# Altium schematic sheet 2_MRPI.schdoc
size 307 x 218 mm; Symbol: Drawing-Symbol_A4; Device: Drawing-Symbol_A4; @Project Name: Avian; @Page Count: 2; @Update Date: 2026-02-01; @Create Date: 2026-01-29; @Schematic Name: Avian_1; @Page No: 2; @Page Name: MRPI; Company: EasyEDA.com; Version: V1.0; Page Size: A4; @Create Time: 14:50:30; @Update Time: 21:39:11; Width: 1170; Height: 825; Region Start: 1; X Region Count: 6; Y Region Count: 4; Blade Width: 10; Title Block Position: 3; @Board Name: Avian_1
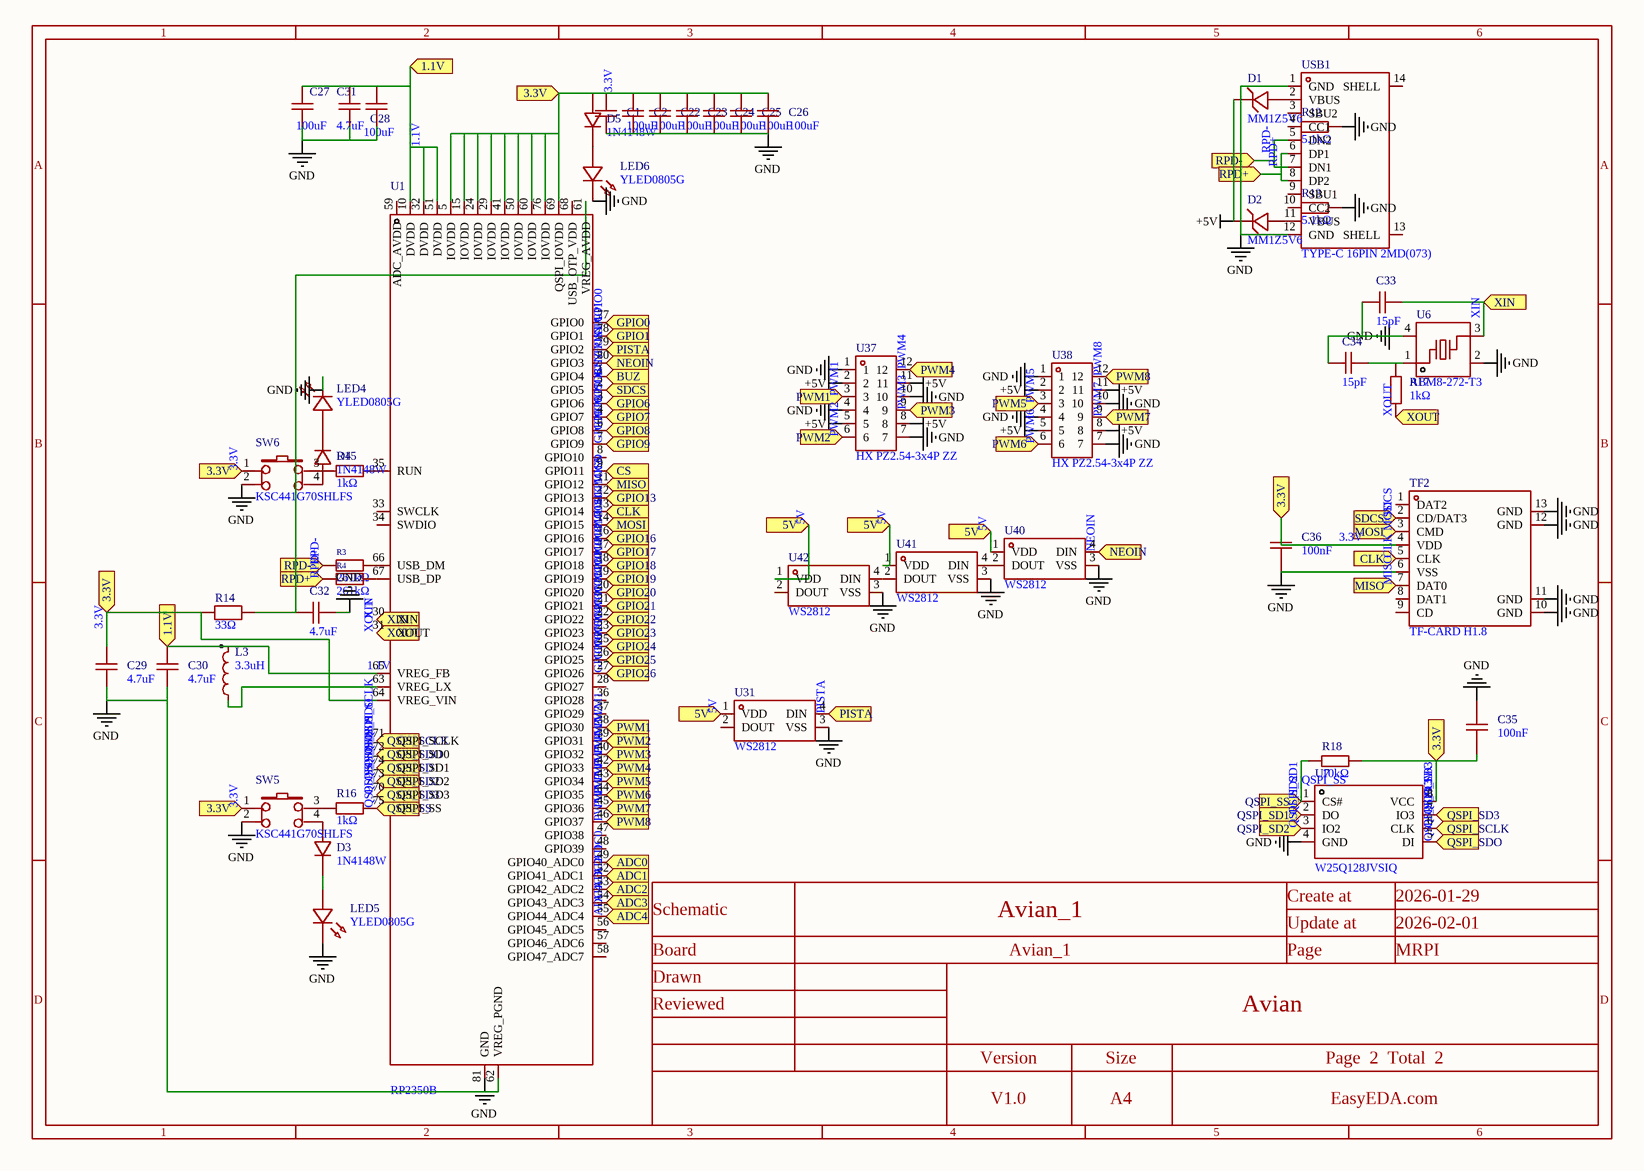
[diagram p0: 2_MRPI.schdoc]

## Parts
C1  100uF  [C1206]
C2  100uF  [C1206]
C22  100uF  [C1206]
C23  100uF  [C1206]
C24  100uF  [C1206]
C25  100uF  [C1206]
C26  100uF  [C1206]
C27  100uF  [C1206]
C28  100uF  [C1206]
C29  4.7uF  [C1206]
C30  4.7uF  [C1206]
C31  4.7uF  [C1206]
C32  4.7uF  [C1206]
C33  15pF  [C0603]
C34  15pF  [C0603]
C35  100nF  [C0603]
C36  100nF  [C0603]
D1  MM1Z5V6  [SOD-123_L2.8-W1.8-LS3.7-RD]
D2  MM1Z5V6  [SOD-123_L2.8-W1.8-LS3.7-RD]
D3  1N4148W  [SOD-123F_L2.7-W1.6-LS3.8-RD]
D4  1N4148W  [SOD-123F_L2.7-W1.6-LS3.8-RD]
D5  1N4148W  [SOD-123F_L2.7-W1.6-LS3.8-RD]
L3  3.3uH  [IND-SMD_L2.0-W1.6_AOTA-B201610S3R3-101-T]
LED4  YLED0805G  [LED0805-FD-GREEN]
LED5  YLED0805G  [LED0805-FD-GREEN]
LED6  YLED0805G  [LED0805-FD-GREEN]
R3  261kΩ  [R0603]
R4  261kΩ  [R0603]
R12  5.1kΩ  [R0805]
R13  5.1kΩ  [R0805]
R14  33Ω  [R0603]
R15  1kΩ  [R0603]
R16  1kΩ  [R0603]
R17  1kΩ  [R0603]
R18  10kΩ  [R0603]
SW5  KSC441G70SHLFS  [KEY--SMD_4P-L6.2-W6.2-P4.50-LS12.0]
SW6  KSC441G70SHLFS  [KEY--SMD_4P-L6.2-W6.2-P4.50-LS12.0]
TF2  TF-CARD H1.8  [TF-SMD_TF-CARD-H1.8]
U1  RP2350B  [QFN-80_L10.0-W10.0-P0.40-TL-EP3.4]
U6  ABM8-272-T3  [CRYSTAL-SMD_4P-L3.2-W2.5-BL]
U7  W25Q128JVSIQ  [SOIC-8_L5.3-W5.3-P1.27-LS8.0-BL]
U31  WS2812  [LED-SMD_4P-L5.0-W5.0-TL-A]
U37  HX PZ2.54-3x4P ZZ  [HDR-TH_12P-P2.54-V-M-R3-C4-S2.54]
U38  HX PZ2.54-3x4P ZZ  [HDR-TH_12P-P2.54-V-M-R3-C4-S2.54]
U40  WS2812  [LED-SMD_4P-L5.0-W5.0-TL-A]
U41  WS2812  [LED-SMD_4P-L5.0-W5.0-TL-A]
U42  WS2812  [LED-SMD_4P-L5.0-W5.0-TL-A]
USB1  TYPE-C 16PIN 2MD(073)  [USB-C-SMD_TYPE-C-6PIN-2MD-073]

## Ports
1.1V (in), 3.3V (in), 5V (in), ADC0 (in), ADC1 (in), ADC2 (in), ADC3 (in), ADC4 (in), BUZ (in), CLK (in), CS (in), GPIO0 (in), GPIO1 (in), GPIO6 (in), GPIO7 (in), GPIO8 (in), GPIO9 (in), GPIO13 (in), GPIO16 (in), GPIO17 (in), GPIO18 (in), GPIO19 (in), GPIO20 (in), GPIO21 (in), GPIO22 (in), GPIO23 (in), GPIO24 (in), GPIO25 (in), GPIO26 (in), MISO (in), MOSI (in), NEOIN (in), PISTA (in), PWM1 (in), PWM2 (in), PWM3 (in), PWM4 (in), PWM5 (in), PWM6 (in), PWM7 (in), PWM8 (in), QSPI_SCLK (in), QSPI_SD1 (in), QSPI_SD2 (in), QSPI_SD3 (in), QSPI_SDO (in), QSPI_SS (in), RPD+ (in), RPD- (in), SDCS (in), XIN (in), XOUT (in)

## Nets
+5V: D1.1(K) D2.1(K) U37.2 U37.5 U37.8 U37.11 U38.2 U38.5 U38.8 U38.11
GND: C1.1 C2.1 C22.1 C23.1 C24.1 C25.1 C26.1 C27.1 C28.1 C29.1 C30.1 C31.1 C32.2 C33.1 C34.1 C35.2 C36.1 LED4.2(K) LED5.2(K) LED6.2(K) R12.2 R13.2 SW5.2 SW6.2 TF2.6(VSS) TF2.10(GND) TF2.11(GND) TF2.12(GND) TF2.13(GND) U1.62(VREG_PGND) U1.81(GND) U6.2(GND) U6.4(GND) U7.4(GND) U31.3(VSS) U37.1 U37.4 U37.7 U37.10 U38.1 U38.4 U38.7 U38.10 U40.3(VSS) U41.3(VSS) U42.3(VSS) USB1.1(GND) USB1.12(GND)
1.1V: C27.2 C28.2 C30.2 C31.2 L3.2 U1.10(DVDD) U1.32(DVDD) U1.51(DVDD) U1.65(VREG_FB) ; port 1.1V
3.3V: C1.2 C2.2 C22.2 C23.2 C24.2 C25.2 C26.2 C29.2 C35.1 C36.2 D5.2(A) R14.1 R18.2 SW5.1 SW6.1 TF2.4(VDD) U1.5(IOVDD) U1.15(IOVDD) U1.24(IOVDD) U1.29(IOVDD) U1.41(IOVDD) U1.50(IOVDD) U1.60(IOVDD) U1.64(VREG_VIN) U1.69(QSPI_IOVDD) U1.76(IOVDD) U7.8(VCC) ; port 3.3V
5V: U31.1(VDD) U40.1(VDD) U41.1(VDD) U42.1(VDD) ; port 5V
ADC0: U1.49(GPIO40_ADC0) ; port ADC0
ADC1: U1.52(GPIO41_ADC1) ; port ADC1
ADC2: U1.53(GPIO42_ADC2) ; port ADC2
ADC3: U1.54(GPIO43_ADC3) ; port ADC3
ADC4: U1.55(GPIO44_ADC4) ; port ADC4
BUZ: U1.1(GPIO4) ; port BUZ
CLK: TF2.5(CLK) U1.13(GPIO14) ; port CLK
CS: U1.9(GPIO11) ; port CS
GPIO0: U1.77(GPIO0) ; port GPIO0
GPIO1: U1.78(GPIO1) ; port GPIO1
GPIO6: U1.3(GPIO6) ; port GPIO6
GPIO7: U1.4(GPIO7) ; port GPIO7
GPIO8: U1.6(GPIO8) ; port GPIO8
GPIO9: U1.7(GPIO9) ; port GPIO9
GPIO13: U1.12(GPIO13) ; port GPIO13
GPIO16: U1.16(GPIO16) ; port GPIO16
GPIO17: U1.17(GPIO17) ; port GPIO17
GPIO18: U1.18(GPIO18) ; port GPIO18
GPIO19: U1.19(GPIO19) ; port GPIO19
GPIO20: U1.20(GPIO20) ; port GPIO20
GPIO21: U1.21(GPIO21) ; port GPIO21
GPIO22: U1.22(GPIO22) ; port GPIO22
GPIO23: U1.23(GPIO23) ; port GPIO23
GPIO24: U1.25(GPIO24) ; port GPIO24
GPIO25: U1.26(GPIO25) ; port GPIO25
GPIO26: U1.27(GPIO26) ; port GPIO26
MISO: TF2.7(DAT0) U1.11(GPIO12) ; port MISO
MOSI: TF2.3(CMD) U1.14(GPIO15) ; port MOSI
NEOIN: U1.80(GPIO3) U40.4(DIN) ; port NEOIN
PISTA: U1.79(GPIO2) U31.4(DIN) ; port PISTA
PWM1: U1.38(GPIO30) U37.3 ; port PWM1
PWM2: U1.39(GPIO31) U37.6 ; port PWM2
PWM3: U1.40(GPIO32) U37.9 ; port PWM3
PWM4: U1.42(GPIO33) U37.12 ; port PWM4
PWM5: U1.43(GPIO34) U38.3 ; port PWM5
PWM6: U1.44(GPIO35) U38.6 ; port PWM6
PWM7: U1.45(GPIO36) U38.9 ; port PWM7
PWM8: U1.46(GPIO37) U38.12 ; port PWM8
QSPI_SCLK: U1.71(QSPI_SCLK) U7.6(CLK) ; port QSPI_SCLK
QSPI_SD1: U1.74(QSPI_SD1) U7.2(DO) ; port QSPI_SD1
QSPI_SD2: U1.73(QSPI_SD2) U7.3(IO2) ; port QSPI_SD2
QSPI_SD3: U1.70(QSPI_SD3) U7.7(IO3) ; port QSPI_SD3
QSPI_SDO: U1.72(QSPI_SD0) U7.5(DI) ; port QSPI_SDO
QSPI_SS: R16.2 R18.1 U1.75(QSPI_SS) U7.1(CS#) ; port QSPI_SS
RPD+: R3.1 R4.1 USB1.5(DN2) USB1.6(DP1) USB1.7(DN1) USB1.8(DP2) ; port RPD-, port RPD+  [also labelled RPD-]
SDCS: TF2.2(CD/DAT3) U1.2(GPIO5) ; port SDCS
XIN: C33.2 U1.30(XIN) U6.3 ; port XIN
XOUT: R17.1 U1.31(XOUT) ; port XOUT
NetC32_1: C32.1 R14.2 U1.61(VREG_AVDD)
NetC34_2: C34.2 R17.2 U6.1
NetD1_2: D1.2(A) USB1.2(VBUS)
NetD2_2: D2.2(A) USB1.11(VBUS)
NetD3_1: D3.1(K) LED5.1(A)
NetD3_2: D3.2(A) SW5.4
NetD4_1: D4.1(K) LED4.1(A)
NetD4_2: D4.2(A) SW6.4
NetD5_1: D5.1(K) LED6.1(A)
NetL3_1: L3.1 U1.63(VREG_LX)
NetR3_2: R3.2 U1.66(USB_DM)
NetR4_2: R4.2 U1.67(USB_DP)
NetR12_1: R12.1 USB1.4(CC1)
NetR13_1: R13.1 USB1.10(CC2)
NetR15_1: R15.1 SW6.3
NetR15_2: R15.2 U1.35(RUN)
NetR16_1: R16.1 SW5.3
NetU40_2: U40.2(DOUT) U41.4(DIN)
NetU41_2: U41.2(DOUT) U42.4(DIN)

Not connected (* = marked no-connect by the designer): TF2 1(DAT2) 8(DAT1) 9(CD); U1 8(GPIO10) 28(GPIO27) 33(SWCLK) 34(SWDIO) 36(GPIO28) 37(GPIO29) 47(GPIO38) 48(GPIO39) 56(GPIO45_ADC5) 57(GPIO46_ADC6) 58(GPIO47_ADC7) 59(ADC_AVDD) 68(USB_OTP_VDD); U31 2(DOUT); U42 2(DOUT); USB1 3(SBU2) 9(SBU1) 13(SHELL) 14(SHELL)

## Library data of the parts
C1 C2 C22-C28 = CL31A107MQHNNNE: Manufacturer: SAMSUNG(三星); Add into BOM: yes; Tolerance: ±20%; Voltage Rating: 6.3V; Temperature Coefficient: X5R
C29-C32 = CL31B475KBHNNNE: Manufacturer: SAMSUNG(三星); Add into BOM: yes; Tolerance: ±10%; Voltage Rating: 50V; Temperature Coefficient: X7R
C33 C34 = CL10C150JB8NNNC: Manufacturer: SAMSUNG(三星); Add into BOM: yes; Tolerance: ±5%; Voltage Rating: 50V; Temperature Coefficient: C0G
C35 C36 = CC0603KRX7R9BB104: Manufacturer: YAGEO(国巨); Add into BOM: yes; Tolerance: ±10%; Voltage Rating: 50V; Temperature Coefficient: X7R
D1 D2 = MM1Z5V6_C85210: Manufacturer: ST(先科); Add into BOM: yes; Diode Configuration: Independent Type; Zener Voltage (Nom): 5.6V; Reverse Leakage Current (Ir): 1uA@2.5V; Zener Voltage (Range): 5.2V~6V; Power Dissipation: 500mW; Zener Impedance (Zzt): 80Ω
D3-D5 = 1N4148W_C81598: Manufacturer: ST(先科); Add into BOM: yes; Diode Configuration: Independent; Voltage - Forward(Vf@If): 1V@50mA; Voltage - DC Reverse(Vr): 75V; Current - Rectified: 150mA; Pd - Power Dissipation: 400mW; Reverse Leakage Current (Ir): 1uA@75V; Reverse Recovery Time (trr): 4ns; Non-Repetitive Peak Forward Surge Current: 1A
L3 = AOTA-B201610S3R3-101-T: Manufacturer: ABRACON; Add into BOM: yes; Current Rating: 2.1A; Current - Saturation(Isat): 2.4A; DC Resistance(DCR): 115mΩ; Type: Molded Inductor
LED4-LED6 = YLED0805G: Manufacturer: YONGYUTAI(永裕泰); Add into BOM: yes; Lamp Holder Type: -；-; Illumination Color: Emerald Green; Voltage - Forward(Vf): 2.4V~3.1V; Power(Watts): 70mW; Forward Current: 20mA; Wavelength - Dominant: 516nm~534nm; Peak Wavelength: 525nm; Luminous Intensity: 430mcd; Viewing Angle: 120°
R3 R4 = 0603WAF2613T5E: Manufacturer: UNI-ROYAL(厚声); Add into BOM: yes; Tolerance: ±1%; Temperature Coefficient: ±100ppm/℃
R12 R13 = 0805W8F5101T5E: Manufacturer: UNI-ROYAL(厚声); Add into BOM: yes; Tolerance: ±1%; Power(Watts): 125mW; Voltage-Supply(Max): 150V; Temperature Coefficient: ±100ppm/℃
R14 = FRC0603F33R0TS: Manufacturer: FOJAN(富捷); Add into BOM: yes; Tolerance: ±1%; Power(Watts): 100mW; Voltage-Supply(Max): 75V; Temperature Coefficient: ±100ppm/℃
R15-R17 = RC0603FR-071KL: Manufacturer: YAGEO(国巨); Add into BOM: yes; Tolerance: ±1%; Power(Watts): 100mW; Voltage-Supply(Max): 75V; Temperature Coefficient: ±100ppm/℃
R18 = RC0603FR-0710KL: Manufacturer: YAGEO(国巨); Add into BOM: yes; Tolerance: ±1%; Temperature Coefficient: ±100ppm/℃
SW5 SW6 = KSC441G70SHLFS: Manufacturer: C&K; Add into BOM: yes; Circuit: SPST; Actuator Style: Round Button; Operating Force: 4N; Switch Height: 5.2mm; Contact Current: 50mA; Voltage Rating: 32V; IP Rating: IP67
TF2 = TF-CARD H1.8: Manufacturer: SHOU HAN(首韩); Add into BOM: yes; Card Connection Mode: Push-Push; Card Type: MicroSD Card (TF Card); Connector Type: Connector and Ejector
U1 = RP2350B_C42415655: Manufacturer: Raspberry Pi(树莓派); Add into BOM: yes
U6 = ABM8-272-T3_C20625731: Manufacturer: ABRACON; Add into BOM: yes
U7 = W25Q128JVSIQ: Manufacturer: Winbond(华邦); Symbol: W25Q128JVSIQTR; Add into BOM: yes; Interface: SPI; Memory Size: 128Mbit; Clock Frequency: 133MHz; Voltage - Supply: 2.7V~3.6V; Standby Supply Current: 1uA; Program / Erase Cycles: 100,000 Cycles; Page Programming Time (Tpp): 3ms; Block Erase Time(tBE): 120ms@(32KB); Data Retention - TDR (Year): 20 Years
U31 U40-U42 = WS2812: Manufacturer: worldsemi; Add into BOM: yes
U37 U38 = HX PZ2.54-3x4P ZZ: Manufacturer: hanxia(韩下); Add into BOM: yes; Pin Structure: 3x4P; Pitch: 2.54mm; Circluar Pins/Square Pins: Pin Header; Current Rating: 3A; Voltage Rating (Max): 1kV
USB1 = TYPE-C 16PIN 2MD(073): Manufacturer: SHOU HAN(首韩); Add into BOM: yes; Gender: Female; Number of Contacts: 16P; Number of Ports: 1; Current Rating-Power: 3A; Voltage Rating: 5V; Connect-Disconnect Life: 5,000 Cycles; Detection color: Black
